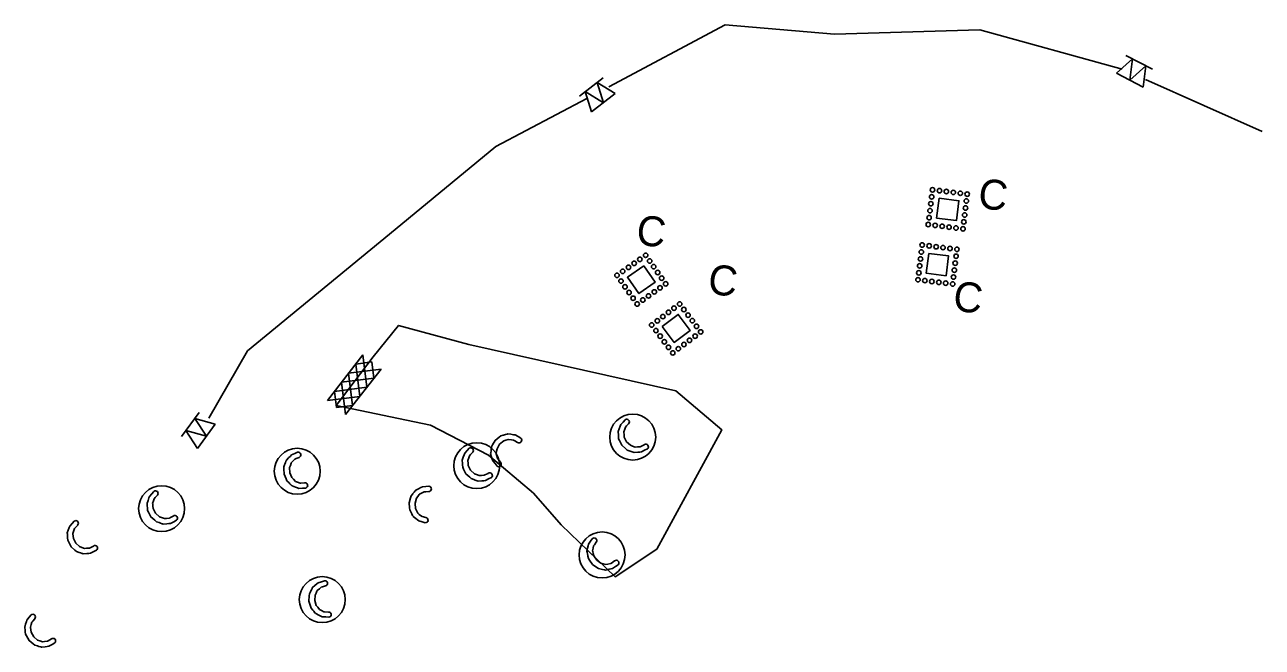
# Model space of a CAD drawing. Extents: x 2470000 to 2520000, y 340000 to 380000.
# Drawn here: x 2482993 to 2483612, y 366094 to 366405 of the extents above; entities that cross this region are included whole.
import ezdxf

# ---------------------------------------------------------------- set-up
doc = ezdxf.new("R2010")
doc.units = 0
for name, color, linetype in [('Bare Soil (Coastal) Drainage Area Border FG Drainage', 7, 'Continuous'), ('Coir Fiber Wattle with PAM CG CELL', 7, 'Continuous'), ('Coir Fiber Wattle with PAM Final CELL', 7, 'Continuous'), ('Prop Guardrail', 7, 'Continuous'), ('Rock Silt Check Type A CG CELL', 7, 'Continuous'), ('Scratch_Level_5', 7, 'Continuous'), ('Sheet Data Field CELL', 7, 'Continuous'), ('Special Sediment Control Fence Section Both CELL', 7, 'Continuous'), ('Wattle CG CELL', 7, 'Continuous'), ('Wattle Final CELL', 7, 'Continuous')]:
    doc.layers.add(name, color=color, linetype=linetype)

# ---------------------------------------------------------------- blocks, each defined once
blk = doc.blocks.new('C3')
at = {"layer": 'Prop Guardrail'}
blk.add_text('C', height=0.3, dxfattribs=at).set_placement((-0.161, -0.136))

msp = doc.modelspace()

# ---------------------------------------------------------------- linework, layer by layer
at = {"layer": 'Bare Soil (Coastal) Drainage Area Border FG Drainage'}
msp.add_lwpolyline([(2483167.04, 366238.97), (2483148.48, 366214.61), (2483195.7, 366204.86), (2483224.73, 366189.76), (2483247.18, 366170.71), (2483261.12, 366154.99), (2483288.05, 366128.96), (2483309.01, 366142.75), (2483341.56, 366202.4), (2483318.49, 366222.03), (2483214.91, 366245.15), (2483179.71, 366254.72)], close=True, dxfattribs=at)
at = {"layer": 'Coir Fiber Wattle with PAM CG CELL'}
for p, q in [((2483125.93, 366185.73), (2483125.56, 366184.68)), ((2483125.93, 366185.73), (2483126.01, 366185.95)), ((2483127.01, 366187), (2483126.01, 366185.95)), ((2483127.78, 366187.79), (2483127.01, 366187)), ((2483128.51, 366188.1), (2483127.78, 366187.79)), ((2483129.94, 366188.7), (2483128.51, 366188.1)), ((2483125.17, 366183.56), (2483125.56, 366184.68)), ((2483125.17, 366183.56), (2483125.29, 366180.93)), ((2483125.29, 366180.92), (2483125.29, 366180.93)), ((2483125.29, 366180.92), (2483126.26, 366178.56)), ((2483126.26, 366178.56), (2483127.1, 366177.71)), ((2483127.1, 366177.71), (2483128.11, 366176.68)), ((2483128.11, 366176.68), (2483129.08, 366176.32)), ((2483129.08, 366176.32), (2483130.47, 366175.81)), ((2483130.8, 366175.82), (2483130.47, 366175.81)), ((2483130.8, 366175.82), (2483132.66, 366175.88)), ((2483057.08, 366166.92), (2483056.62, 366165.54)), ((2483057.43, 366167.97), (2483057.08, 366166.92)), ((2483057.96, 366168.56), (2483057.43, 366167.97)), ((2483059, 366169.71), (2483057.96, 366168.56)), ((2483056.65, 366165.31), (2483056.62, 366165.54)), ((2483056.65, 366165.31), (2483056.76, 366164.21)), ((2483056.89, 366163.02), (2483056.76, 366164.21)), ((2483056.89, 366163.02), (2483058.12, 366160.7)), ((2483058.13, 366160.69), (2483058.12, 366160.7)), ((2483058.13, 366160.69), (2483060.01, 366158.98)), ((2483060.01, 366158.98), (2483061.14, 366158.56)), ((2483061.14, 366158.56), (2483062.5, 366158.06)), ((2483062.5, 366158.06), (2483063.52, 366158.16)), ((2483063.52, 366158.16), (2483064.99, 366158.29)), ((2483065.29, 366158.44), (2483064.99, 366158.29)), ((2483065.29, 366158.44), (2483066.94, 366159.29))]:
    msp.add_line(p, q, dxfattribs=at)
for points in [[(2483133.23, 366173.35), (2483131.67, 366173.28), (2483129.86, 366173.19), (2483129.07, 366173.47), (2483128.12, 366173.82), (2483126.43, 366174.43), (2483126.4, 366174.46), (2483126.09, 366174.77), (2483126.03, 366174.82), (2483125.35, 366175.48), (2483124.87, 366175.95), (2483123.82, 366176.97), (2483123.4, 366177.92), (2483122.39, 366180.27), (2483122.39, 366180.28), (2483122.31, 366182.91), (2483122.27, 366183.94), (2483122.68, 366185), (2483122.76, 366185.22), (2483123.1, 366186.12), (2483123.36, 366186.8), (2483123.43, 366186.96), (2483123.56, 366187.3), (2483123.56, 366187.31), (2483124.62, 366188.39), (2483125.56, 366189.34), (2483126.13, 366189.92), (2483127.74, 366190.63), (2483129.16, 366191.25)], [(2483068.54, 366157.25), (2483067.17, 366156.51), (2483065.56, 366155.66), (2483064.73, 366155.58), (2483063.73, 366155.48), (2483061.94, 366155.31), (2483061.9, 366155.33), (2483061.48, 366155.47), (2483061.41, 366155.49), (2483060.51, 366155.8), (2483059.88, 366156.02), (2483058.49, 366156.49), (2483057.71, 366157.18), (2483055.79, 366158.86), (2483055.78, 366158.87), (2483054.58, 366161.21), (2483054.11, 366162.13), (2483054.02, 366163.26), (2483054, 366163.49), (2483053.92, 366164.45), (2483053.87, 366165.18), (2483053.86, 366165.35), (2483053.83, 366165.72), (2483053.83, 366165.73), (2483054.32, 366167.15), (2483054.76, 366168.42), (2483055.03, 366169.18), (2483056.18, 366170.51), (2483057.2, 366171.68)]]:
    msp.add_lwpolyline(points, dxfattribs=at)
for centre in [(2483129, 366181.74), (2483061.13, 366163.02)]:
    msp.add_circle(centre, 11.5, dxfattribs=at)
for centre, radius, start, end in [((2483129.45, 366189.94), 1.33, 291.54348, 102.65612), ((2483132.94, 366174.62), 1.3, 282.65612, 102.65612), ((2483058.02, 366170.63), 1.33, 316.88966, 128.0023), ((2483067.74, 366158.27), 1.3, 308.0023, 128.0023)]:
    msp.add_arc(centre, radius, start, end, dxfattribs=at)
at = {"layer": 'Coir Fiber Wattle with PAM Final CELL'}
for p, q in [((2483293.24, 366203.81), (2483292.88, 366202.77)), ((2483293.77, 366204.4), (2483293.24, 366203.81)), ((2483294.83, 366205.54), (2483293.77, 366204.4)), ((2483292.88, 366202.77), (2483292.4, 366201.4)), ((2483292.42, 366201.17), (2483292.4, 366201.4)), ((2483292.42, 366201.17), (2483292.52, 366200.06)), ((2483292.63, 366198.88), (2483292.52, 366200.06)), ((2483292.63, 366198.88), (2483293.84, 366196.54)), ((2483216.8, 366191.26), (2483215.74, 366190.12)), ((2483293.84, 366196.53), (2483293.84, 366196.54)), ((2483293.84, 366196.53), (2483295.7, 366194.79)), ((2483295.7, 366194.79), (2483296.82, 366194.36)), ((2483296.82, 366194.36), (2483298.17, 366193.85)), ((2483298.17, 366193.85), (2483299.2, 366193.93)), ((2483299.2, 366193.93), (2483300.67, 366194.04)), ((2483300.97, 366194.19), (2483300.67, 366194.04)), ((2483300.97, 366194.19), (2483302.64, 366195.02)), ((2483214.84, 366188.5), (2483214.35, 366187.13)), ((2483214.37, 366186.89), (2483214.35, 366187.13)), ((2483214.37, 366186.89), (2483214.47, 366185.79)), ((2483214.58, 366184.6), (2483214.47, 366185.79)), ((2483215.21, 366189.54), (2483214.84, 366188.5)), ((2483215.74, 366190.12), (2483215.21, 366189.54)), ((2483214.58, 366184.6), (2483215.77, 366182.26)), ((2483215.78, 366182.25), (2483215.77, 366182.26)), ((2483215.78, 366182.25), (2483217.63, 366180.5)), ((2483217.63, 366180.5), (2483218.75, 366180.07)), ((2483218.75, 366180.07), (2483220.1, 366179.55)), ((2483220.1, 366179.55), (2483221.13, 366179.63)), ((2483221.13, 366179.63), (2483222.6, 366179.73)), ((2483222.9, 366179.88), (2483222.6, 366179.73)), ((2483222.9, 366179.88), (2483224.57, 366180.7)), ((2483277.1, 366143.26), (2483276.8, 366141.84)), ((2483276.85, 366141.61), (2483276.8, 366141.84)), ((2483277.33, 366144.34), (2483277.1, 366143.26)), ((2483277.78, 366144.99), (2483277.33, 366144.34)), ((2483278.67, 366146.25), (2483277.78, 366144.99)), ((2483276.85, 366141.61), (2483277.1, 366140.52)), ((2483277.36, 366139.36), (2483277.1, 366140.52)), ((2483277.36, 366139.36), (2483278.85, 366137.2)), ((2483278.86, 366137.19), (2483278.85, 366137.2)), ((2483278.86, 366137.19), (2483280.93, 366135.71)), ((2483280.93, 366135.71), (2483282.1, 366135.42)), ((2483284.51, 366135.3), (2483285.96, 366135.61)), ((2483286.23, 366135.79), (2483285.96, 366135.61)), ((2483286.23, 366135.79), (2483287.78, 366136.83)), ((2483282.1, 366135.42), (2483283.5, 366135.09)), ((2483283.5, 366135.09), (2483284.51, 366135.3)), ((2483140.93, 366123.65), (2483140.09, 366122.93)), ((2483141.69, 366123.88), (2483140.93, 366123.65)), ((2483143.17, 366124.33), (2483141.69, 366123.88)), ((2483137.9, 366119.7), (2483137.75, 366117.07)), ((2483137.75, 366117.06), (2483137.75, 366117.07)), ((2483137.75, 366117.06), (2483138.47, 366114.62)), ((2483137.9, 366119.7), (2483138.41, 366120.78)), ((2483138.88, 366121.78), (2483138.41, 366120.78)), ((2483138.88, 366121.78), (2483138.98, 366122)), ((2483140.09, 366122.93), (2483138.98, 366122)), ((2483138.47, 366114.62), (2483139.22, 366113.68)), ((2483139.22, 366113.68), (2483140.13, 366112.55)), ((2483140.13, 366112.55), (2483141.05, 366112.1)), ((2483141.05, 366112.1), (2483142.38, 366111.45)), ((2483142.71, 366111.43), (2483142.38, 366111.45)), ((2483142.71, 366111.43), (2483144.57, 366111.3))]:
    msp.add_line(p, q, dxfattribs=at)
for points in [[(2483304.21, 366192.95), (2483302.83, 366192.24), (2483301.21, 366191.4), (2483300.38, 366191.33), (2483299.37, 366191.25), (2483297.58, 366191.1), (2483297.54, 366191.12), (2483297.13, 366191.27), (2483297.06, 366191.29), (2483296.16, 366191.61), (2483295.53, 366191.83), (2483294.15, 366192.33), (2483293.37, 366193.02), (2483291.48, 366194.73), (2483291.47, 366194.74), (2483290.3, 366197.1), (2483289.84, 366198.02), (2483289.76, 366199.15), (2483289.75, 366199.39), (2483289.69, 366200.35), (2483289.64, 366201.07), (2483289.63, 366201.25), (2483289.6, 366201.61), (2483289.61, 366201.62), (2483290.12, 366203.04), (2483290.58, 366204.3), (2483290.86, 366205.06), (2483292.03, 366206.37), (2483293.06, 366207.53)], [(2483226.13, 366178.63), (2483224.75, 366177.92), (2483223.13, 366177.09), (2483222.3, 366177.03), (2483221.29, 366176.95), (2483219.5, 366176.81), (2483219.46, 366176.82), (2483219.04, 366176.97), (2483218.97, 366177), (2483218.07, 366177.32), (2483217.45, 366177.55), (2483216.07, 366178.04), (2483215.3, 366178.74), (2483213.41, 366180.46), (2483213.4, 366180.47), (2483212.24, 366182.83), (2483211.78, 366183.76), (2483211.71, 366184.89), (2483211.7, 366185.12), (2483211.64, 366186.08), (2483211.59, 366186.81), (2483211.59, 366186.98), (2483211.56, 366187.35), (2483211.56, 366187.36), (2483212.08, 366188.78), (2483212.55, 366190.04), (2483212.83, 366190.79), (2483214, 366192.1), (2483215.04, 366193.25)], [(2483289.6, 366134.98), (2483288.32, 366134.09), (2483286.83, 366133.06), (2483286.01, 366132.88), (2483285.02, 366132.67), (2483283.27, 366132.29), (2483283.23, 366132.3), (2483282.8, 366132.4), (2483282.72, 366132.41), (2483281.79, 366132.61), (2483281.14, 366132.75), (2483279.71, 366133.06), (2483278.85, 366133.65), (2483276.75, 366135.1), (2483276.74, 366135.11), (2483275.27, 366137.3), (2483274.7, 366138.15), (2483274.48, 366139.26), (2483274.43, 366139.5), (2483274.25, 366140.44), (2483274.11, 366141.16), (2483274.08, 366141.33), (2483274, 366141.69), (2483274, 366141.69), (2483274.33, 366143.17), (2483274.62, 366144.48), (2483274.8, 366145.27), (2483275.79, 366146.72), (2483276.66, 366148)], [(2483144.87, 366108.72), (2483143.32, 366108.81), (2483141.5, 366108.91), (2483140.75, 366109.27), (2483139.84, 366109.71), (2483138.23, 366110.49), (2483138.2, 366110.52), (2483137.92, 366110.86), (2483137.87, 366110.92), (2483137.25, 366111.65), (2483136.83, 366112.16), (2483135.88, 366113.29), (2483135.57, 366114.28), (2483134.8, 366116.71), (2483134.8, 366116.72), (2483134.99, 366119.35), (2483135.06, 366120.38), (2483135.57, 366121.39), (2483135.67, 366121.6), (2483136.11, 366122.46), (2483136.44, 366123.11), (2483136.51, 366123.26), (2483136.68, 366123.59), (2483136.68, 366123.6), (2483137.85, 366124.56), (2483138.88, 366125.42), (2483139.51, 366125.93), (2483141.18, 366126.47), (2483142.65, 366126.94)]]:
    msp.add_lwpolyline(points, dxfattribs=at)
for centre in [(2483296.88, 366198.82), (2483218.82, 366184.53), (2483281.58, 366139.85), (2483141.53, 366117.5)]:
    msp.add_circle(centre, 11.5, dxfattribs=at)
for centre, radius, start, end in [((2483293.86, 366206.47), 1.33, 316.1456, 127.25824), ((2483215.84, 366192.19), 1.33, 315.91864, 127.03127), ((2483303.42, 366193.99), 1.3, 307.25824, 127.25824), ((2483225.35, 366179.67), 1.3, 307.03127, 127.03127), ((2483277.6, 366147.05), 1.33, 323.55632, 134.66896), ((2483288.69, 366135.91), 1.3, 314.66896, 134.66896), ((2483142.81, 366125.62), 1.33, 285.67126, 96.78389), ((2483144.72, 366110.01), 1.3, 276.78389, 96.78389)]:
    msp.add_arc(centre, radius, start, end, dxfattribs=at)
at = {"layer": 'Rock Silt Check Type A CG CELL'}
for p, q in [((2483144.06, 366217.16), (2483161.81, 366239.97)), ((2483166.36, 366236.45), (2483158.24, 366235.4)), ((2483158.24, 366235.4), (2483160.27, 366219.18)), ((2483161.81, 366239.97), (2483163.83, 366223.76)), ((2483166.36, 366236.45), (2483167.37, 366228.3)), ((2483153.18, 366210.07), (2483170.93, 366232.88)), ((2483170.93, 366232.88), (2483154.72, 366230.86)), ((2483154.72, 366230.86), (2483156.71, 366214.61)), ((2483163.83, 366223.76), (2483147.6, 366221.7)), ((2483167.37, 366228.3), (2483151.16, 366226.28)), ((2483151.16, 366226.28), (2483153.18, 366210.07)), ((2483160.27, 366219.18), (2483144.06, 366217.16)), ((2483147.6, 366221.63), (2483148.59, 366213.62)), ((2483156.71, 366214.61), (2483148.59, 366213.62))]:
    msp.add_line(p, q, dxfattribs=at)
at = {"layer": 'Scratch_Level_5'}
for points in [[(2483450.18, 366318.38), (2483460.11, 366317.16), (2483458.89, 366307.24), (2483448.96, 366308.47)], [(2483445.03, 366290.76), (2483454.96, 366289.54), (2483453.74, 366279.61), (2483443.81, 366280.84)], [(2483302.41, 366284.6), (2483308.17, 366276.42), (2483299.99, 366270.67), (2483294.24, 366278.86)], [(2483311.66, 366254.18), (2483319.65, 366260.2), (2483325.66, 366252.21), (2483317.67, 366246.21)]]:
    msp.add_lwpolyline(points, close=True, dxfattribs=at)
for centre in [(2483446.91, 366322.58), (2483450.38, 366322.15), (2483453.86, 366321.73), (2483457.33, 366321.3), (2483460.81, 366320.87), (2483464.28, 366320.45), (2483446.06, 366315.63), (2483446.48, 366319.1), (2483463.85, 366316.97), (2483445.2, 366308.68), (2483445.63, 366312.16), (2483463, 366310.02), (2483463.43, 366313.5), (2483444.78, 366305.21), (2483448.25, 366304.78), (2483451.72, 366304.36), (2483455.2, 366303.93), (2483458.67, 366303.5), (2483462.15, 366303.08), (2483462.57, 366306.55), (2483303.34, 366289.84), (2483441.33, 366291.48), (2483441.76, 366294.96), (2483445.24, 366294.53), (2483448.71, 366294.1), (2483452.18, 366293.68), (2483455.66, 366293.25), (2483458.7, 366289.35), (2483459.13, 366292.82), (2483294.75, 366283.81), (2483297.61, 366285.82), (2483300.47, 366287.83), (2483305.35, 366286.98), (2483307.36, 366284.12), (2483440.48, 366284.53), (2483440.91, 366288.01), (2483458.28, 366285.87), (2483289.02, 366279.78), (2483291.03, 366276.92), (2483291.88, 366281.79), (2483309.37, 366281.25), (2483311.39, 366278.39), (2483439.63, 366277.59), (2483440.05, 366281.06), (2483443.1, 366277.16), (2483457.42, 366278.93), (2483457.85, 366282.4), (2483293.05, 366274.05), (2483295.06, 366271.19), (2483307.67, 366271.5), (2483310.54, 366273.51), (2483313.4, 366275.53), (2483446.58, 366276.73), (2483450.05, 366276.31), (2483453.52, 366275.88), (2483457, 366275.45), (2483297.07, 366268.33), (2483299.08, 366265.46), (2483301.95, 366267.48), (2483304.81, 366269.49), (2483320.37, 366265.46), (2483311.98, 366259.15), (2483314.78, 366261.25), (2483317.57, 366263.36), (2483322.47, 366262.67), (2483324.58, 366259.87), (2483306.39, 366254.93), (2483308.5, 366252.14), (2483309.19, 366257.04), (2483326.69, 366257.08), (2483328.79, 366254.28), (2483310.6, 366249.34), (2483312.71, 366246.55), (2483325.31, 366247.27), (2483328.1, 366249.38), (2483330.9, 366251.48), (2483314.81, 366243.75), (2483316.92, 366240.96), (2483319.71, 366243.06), (2483322.51, 366245.17)]:
    msp.add_circle(centre, 1.12, dxfattribs=at)
at = {"layer": 'Sheet Data Field CELL'}
for p, q in [((2483284.9, 366374.08), (2483343.17, 366405.21)), ((2483397.82, 366400.42), (2483343.17, 366405.21)), ((2483470.52, 366402.67), (2483397.82, 366400.42)), ((2483541.87, 366382.97), (2483470.52, 366402.67)), ((2483611.93, 366351.79), (2483553.55, 366377.83)), ((2483273.85, 366368.24), (2483228.46, 366344.25)), ((2483175.18, 366300.47), (2483228.46, 366344.25)), ((2483104.18, 366242.08), (2483175.18, 366300.47)), ((2483084.76, 366208.37), (2483104.18, 366242.08))]:
    msp.add_line(p, q, dxfattribs=at)
at = {"layer": 'Special Sediment Control Fence Section Both CELL'}
for p, q in [((2483543.66, 366389.84), (2483556.96, 366382.9)), ((2483270.17, 366369.54), (2483282.08, 366378.66)), ((2483539.03, 366380.98), (2483552.33, 366374.03)), ((2483276.25, 366361.6), (2483288.16, 366370.72)), ((2483071.03, 366199.16), (2483079.95, 366211.21)), ((2483079.06, 366193.21), (2483087.99, 366205.27))]:
    msp.add_line(p, q, dxfattribs=at)
for points in [[(2483539.03, 366380.98), (2483546.99, 366388.11), (2483545.68, 366377.51)], [(2483545.68, 366377.51), (2483553.64, 366384.63), (2483552.33, 366374.03)], [(2483276.25, 366361.6), (2483273.15, 366371.82), (2483282.21, 366366.16)], [(2483282.21, 366366.16), (2483279.1, 366376.38), (2483288.16, 366370.72)], [(2483083.53, 366199.24), (2483077.72, 366208.2), (2483087.99, 366205.27)], [(2483079.06, 366193.21), (2483073.26, 366202.17), (2483083.53, 366199.24)]]:
    msp.add_lwpolyline(points, dxfattribs=at)
at = {"layer": 'Wattle CG CELL'}
for p, q in [((2483234.52, 366197.59), (2483233.46, 366197.26)), ((2483234.52, 366197.59), (2483234.74, 366197.66)), ((2483236.18, 366197.48), (2483234.74, 366197.66)), ((2483237.28, 366197.35), (2483236.18, 366197.48)), ((2483228.79, 366191.85), (2483228.57, 366190.43)), ((2483228.97, 366193.04), (2483228.79, 366191.85)), ((2483230.28, 366195.22), (2483228.97, 366193.04)), ((2483230.28, 366195.22), (2483230.29, 366195.23)), ((2483232.32, 366196.9), (2483230.29, 366195.23)), ((2483232.32, 366196.9), (2483233.46, 366197.26)), ((2483237.96, 366196.95), (2483237.28, 366197.35)), ((2483239.3, 366196.16), (2483237.96, 366196.95)), ((2483228.57, 366190.43), (2483228.86, 366189.44)), ((2483228.86, 366189.44), (2483229.29, 366188.02)), ((2483229.5, 366187.76), (2483229.29, 366188.02)), ((2483229.5, 366187.76), (2483230.66, 366186.31)), ((2483188.67, 366168.22), (2483187.95, 366165.69)), ((2483188.67, 366168.22), (2483189.4, 366169.16)), ((2483190.09, 366170.03), (2483189.4, 366169.16)), ((2483190.09, 366170.03), (2483190.23, 366170.22)), ((2483191.52, 366170.89), (2483190.23, 366170.22)), ((2483192.5, 366171.4), (2483191.52, 366170.89)), ((2483193.29, 366171.46), (2483192.5, 366171.4)), ((2483194.84, 366171.57), (2483193.29, 366171.46)), ((2483187.95, 366165.68), (2483187.95, 366165.69)), ((2483187.95, 366165.68), (2483188.11, 366163.14)), ((2483188.11, 366163.14), (2483188.63, 366162.06)), ((2483188.63, 366162.06), (2483189.26, 366160.76)), ((2483189.26, 366160.76), (2483190.07, 366160.11)), ((2483190.07, 366160.11), (2483191.22, 366159.19)), ((2483191.54, 366159.09), (2483191.22, 366159.19)), ((2483191.54, 366159.09), (2483193.32, 366158.55)), ((2482995.84, 366105.09), (2482995.42, 366103.7)), ((2482996.15, 366106.15), (2482995.84, 366105.09)), ((2482996.66, 366106.76), (2482996.15, 366106.15)), ((2482997.65, 366107.95), (2482996.66, 366106.76)), ((2482995.46, 366103.47), (2482995.42, 366103.7)), ((2482995.46, 366103.47), (2482995.61, 366102.37)), ((2482995.78, 366101.19), (2482995.61, 366102.37)), ((2482995.78, 366101.19), (2482997.09, 366098.91)), ((2482997.1, 366098.9), (2482997.09, 366098.91)), ((2482997.1, 366098.9), (2482999.03, 366097.25)), ((2482999.03, 366097.25), (2483000.18, 366096.87)), ((2483000.18, 366096.87), (2483001.55, 366096.42)), ((2483001.55, 366096.42), (2483002.57, 366096.55)), ((2483002.57, 366096.55), (2483004.04, 366096.74)), ((2483004.33, 366096.9), (2483004.04, 366096.74)), ((2483004.33, 366096.9), (2483005.95, 366097.81))]:
    msp.add_line(p, q, dxfattribs=at)
for points in [[(2483228.97, 366184.34), (2483227.98, 366185.54), (2483226.82, 366186.94), (2483226.58, 366187.74), (2483226.29, 366188.71), (2483225.77, 366190.43), (2483225.77, 366190.47), (2483225.83, 366190.9), (2483225.84, 366190.98), (2483225.96, 366191.93), (2483226.05, 366192.59), (2483226.24, 366194.04), (2483226.75, 366194.95), (2483228.02, 366197.16), (2483228.03, 366197.17), (2483230.09, 366198.81), (2483230.9, 366199.45), (2483231.99, 366199.76), (2483232.21, 366199.83), (2483233.14, 366200.09), (2483233.84, 366200.29), (2483234.01, 366200.34), (2483234.36, 366200.44), (2483234.37, 366200.44), (2483235.86, 366200.23), (2483237.19, 366200.05), (2483238, 366199.94), (2483239.52, 366199.07), (2483240.87, 366198.31)], [(2483193.05, 366155.97), (2483191.55, 366156.4), (2483189.8, 366156.9), (2483189.15, 366157.41), (2483188.36, 366158.05), (2483186.96, 366159.16), (2483186.94, 366159.2), (2483186.73, 366159.59), (2483186.7, 366159.66), (2483186.26, 366160.51), (2483185.96, 366161.1), (2483185.29, 366162.41), (2483185.2, 366163.44), (2483184.99, 366165.99), (2483184.99, 366166), (2483185.75, 366168.52), (2483186.05, 366169.51), (2483186.77, 366170.38), (2483186.92, 366170.57), (2483187.53, 366171.31), (2483188, 366171.87), (2483188.11, 366172), (2483188.34, 366172.28), (2483188.35, 366172.29), (2483189.7, 366172.97), (2483190.89, 366173.58), (2483191.62, 366173.94), (2483193.37, 366174.09), (2483194.91, 366174.23)], [(2483007.62, 366095.82), (2483006.27, 366095.04), (2483004.7, 366094.13), (2483003.87, 366094.02), (2483002.87, 366093.89), (2483001.09, 366093.66), (2483001.05, 366093.67), (2483000.63, 366093.8), (2483000.56, 366093.82), (2482999.64, 366094.1), (2482999, 366094.29), (2482997.6, 366094.72), (2482996.79, 366095.37), (2482994.82, 366096.99), (2482994.81, 366097), (2482993.53, 366099.3), (2482993.03, 366100.2), (2482992.9, 366101.32), (2482992.87, 366101.56), (2482992.76, 366102.52), (2482992.68, 366103.24), (2482992.67, 366103.41), (2482992.62, 366103.78), (2482992.62, 366103.78), (2482993.07, 366105.23), (2482993.47, 366106.51), (2482993.71, 366107.28), (2482994.82, 366108.65), (2482995.79, 366109.85)]]:
    msp.add_lwpolyline(points, dxfattribs=at)
for centre, radius, start, end in [((2483240, 366197.29), 1.33, 238.29367, 49.4063), ((2483229.81, 366185.32), 1.3, 229.4063, 49.4063), ((2483194.77, 366172.9), 1.33, 272.90965, 84.02228), ((2483193.18, 366157.26), 1.3, 264.02228, 84.02228), ((2482996.65, 366108.83), 1.33, 318.85921, 129.97185), ((2483006.79, 366096.81), 1.3, 309.97185, 129.97185)]:
    msp.add_arc(centre, radius, start, end, dxfattribs=at)
at = {"layer": 'Wattle Final CELL'}
for p, q in [((2483019.11, 366154.78), (2483018.06, 366153.64)), ((2483017.17, 366152.01), (2483016.7, 366150.63)), ((2483016.73, 366150.4), (2483016.7, 366150.63)), ((2483016.73, 366150.4), (2483016.83, 366149.29)), ((2483016.95, 366148.11), (2483016.83, 366149.29)), ((2483016.95, 366148.11), (2483018.17, 366145.77)), ((2483017.53, 366153.05), (2483017.17, 366152.01)), ((2483018.06, 366153.64), (2483017.53, 366153.05)), ((2483018.17, 366145.77), (2483018.17, 366145.77)), ((2483018.17, 366145.77), (2483020.04, 366144.04)), ((2483020.04, 366144.04), (2483021.17, 366143.61)), ((2483021.17, 366143.61), (2483022.52, 366143.11)), ((2483022.52, 366143.11), (2483023.54, 366143.19)), ((2483023.54, 366143.19), (2483025.02, 366143.32)), ((2483025.32, 366143.47), (2483025.02, 366143.32)), ((2483025.32, 366143.47), (2483026.98, 366144.3))]:
    msp.add_line(p, q, dxfattribs=at)
msp.add_lwpolyline([(2483028.56, 366142.25), (2483027.18, 366141.52), (2483025.57, 366140.68), (2483024.74, 366140.61), (2483023.73, 366140.52), (2483021.94, 366140.36), (2483021.9, 366140.38), (2483021.49, 366140.52), (2483021.42, 366140.55), (2483020.51, 366140.86), (2483019.88, 366141.08), (2483018.5, 366141.57), (2483017.72, 366142.26), (2483015.82, 366143.95), (2483015.81, 366143.96), (2483014.62, 366146.32), (2483014.16, 366147.24), (2483014.08, 366148.37), (2483014.06, 366148.6), (2483014, 366149.56), (2483013.95, 366150.29), (2483013.94, 366150.46), (2483013.91, 366150.83), (2483013.91, 366150.84), (2483014.42, 366152.26), (2483014.87, 366153.52), (2483015.14, 366154.29), (2483016.3, 366155.6), (2483017.33, 366156.76)], dxfattribs=at)
for centre, radius, start in [((2483018.14, 366155.7), 1.33, 316.4492), ((2483027.77, 366143.28), 1.3, 307.56184)]:
    msp.add_arc(centre, radius, start, 127.56184, dxfattribs=at)

# ---------------------------------------------------------------- block references
at = {"layer": 'Scratch_Level_5', "xscale": 49.99999999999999, "yscale": 50.00000000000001, "rotation": -6.997703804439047}
for p in [(2483478.01, 366319.4), (2483306.93, 366301.11), (2483342.81, 366276.48), (2483465.48, 366268.03)]:
    msp.add_blockref('C3', p, dxfattribs=at)

doc.saveas('drawing.dxf')
